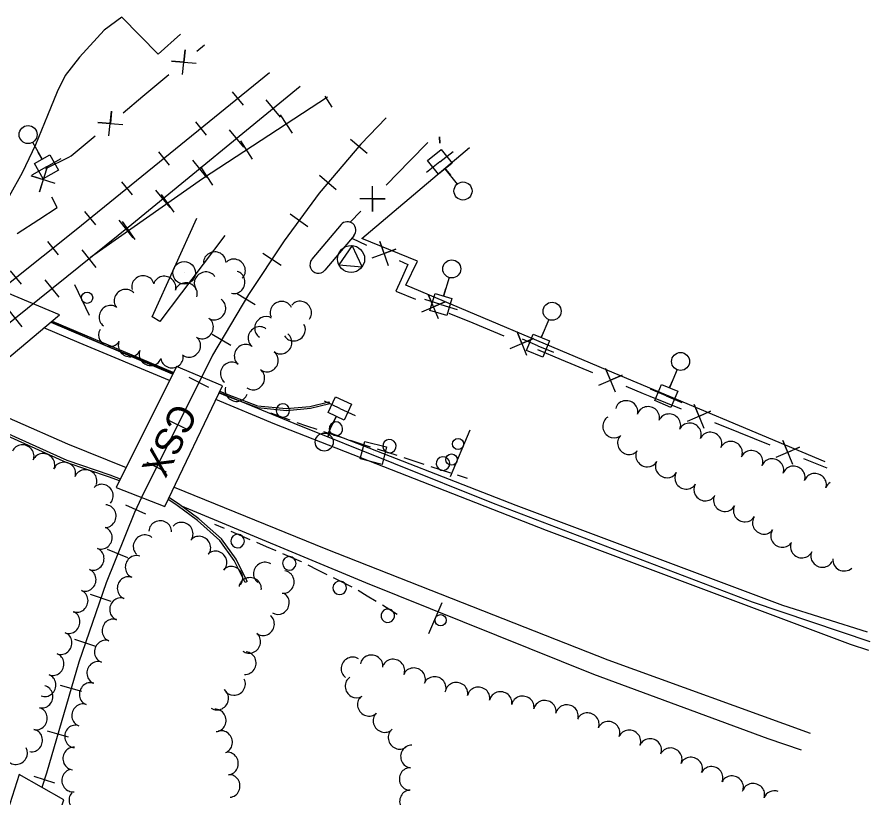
# Model space of a CAD drawing. Extents: x 1746010 to 1754829, y 655801 to 663091.
# Drawn here: x 1752063.6 to 1752442, y 658941.3 to 659287.8 of the extents above; entities that cross this region are included whole.
import ezdxf

# ---------------------------------------------------------------- set-up
doc = ezdxf.new("R2010")
doc.units = 0
for name, color, linetype in [('SURVEY - AERIAL SURVEY - Photo Control - Points - Elevations', 7, 'Continuous'), ('SURVEY - AERIAL SURVEY - Photo Control - Points - Locators', 7, 'Continuous'), ('SURVEY - AERIAL SURVEY - Photo Control - Points - Numbers', 7, 'Continuous'), ('SURVEY - AERIAL SURVEY - Photo Control with Text', 7, 'Continuous'), ('SURVEY - CENTERLINE - Existing Roads - Development', 7, 'Continuous'), ('SURVEY - CENTERLINE - Existing Roads Curve Text', 7, 'Continuous'), ('SURVEY - CENTERLINE - Existing Roads Text', 7, 'Continuous'), ('SURVEY - CENTERLINE - Preliminary - Development', 7, 'Continuous'), ('SURVEY - CONTROL - Points - Numbers', 7, 'Continuous')]:
    doc.layers.add(name, color=color, linetype=linetype)

msp = doc.modelspace()

# ---------------------------------------------------------------- linework, layer by layer
at = {"layer": 'SURVEY - AERIAL SURVEY - Photo Control - Points - Elevations'}
for points in [[(1752045.59, 659171.03), (1751992.27, 659126.33), (1752029.04, 659110.92), (1752082.37, 659155.62)], [(1752082.37, 659155.62), (1752045.59, 659171.03)], [(1752134.28, 659132.71), (1752107.47, 659078.99), (1752129.2, 659070.66), (1752154.72, 659124.15)], [(1752154.72, 659124.15), (1752134.28, 659132.71)], [(1752441.01, 659014.9), (1752403.45, 659026.77), (1752285.01, 659071.08), (1752202.29, 659103.35), (1752201.39, 659101.6)], [(1752064.54, 658951.68), (1752045.7, 658893.16), (1752065.48, 658882.04), (1752084.32, 658940.56)], [(1752084.32, 658940.56), (1752064.54, 658951.68)]]:
    msp.add_lwpolyline(points, dxfattribs=at)
at = {"layer": 'SURVEY - AERIAL SURVEY - Photo Control - Points - Locators'}
for p, q in [((1752164.02, 659248.7), (1752159.23, 659254.59)), ((1752173.98, 659251.09), (1752180.31, 659243.38)), ((1752203.39, 659247.84), (1752200.27, 659252.59)), ((1752185.73, 659236.29), (1752180.45, 659244.34)), ((1752147.63, 659235.41), (1752142.84, 659241.3)), ((1752157.67, 659237.71), (1752163.99, 659229.99)), ((1752168.07, 659224.74), (1752162.79, 659232.79)), ((1752218.9, 659227.18), (1752211.5, 659233.49)), ((1752131.24, 659222.12), (1752126.45, 659228.01)), ((1752141.35, 659224.33), (1752147.68, 659216.61)), ((1752150.41, 659213.19), (1752145.13, 659221.24)), ((1752205.23, 659211.11), (1752197.83, 659217.43)), ((1752114.85, 659208.83), (1752110.06, 659214.72)), ((1752125.04, 659210.95), (1752131.36, 659203.23)), ((1752133.23, 659201.24), (1752127.67, 659209.1)), ((1752098.46, 659195.54), (1752093.67, 659201.43)), ((1752192.65, 659194.65), (1752184.8, 659200.38)), ((1752108.74, 659197.63), (1752114.98, 659189.84)), ((1752115.94, 659189.13), (1752110.39, 659197)), ((1752081.97, 659182.33), (1752077.23, 659188.26)), ((1752092.28, 659184.43), (1752098.52, 659176.64)), ((1752180.69, 659177.55), (1752172.58, 659182.9)), ((1752065.45, 659169.2), (1752060.71, 659175.13)), ((1752075.81, 659171.23), (1752082.05, 659163.45)), ((1752169.24, 659160.09), (1752160.89, 659165.07)), ((1752059.42, 659158.11), (1752065.66, 659150.32)), ((1752158.42, 659141.98), (1752150.07, 659146.95)), ((1752148.6, 659123.48), (1752139.9, 659127.81)), ((1752139.27, 659104.67), (1752130.56, 659109)), ((1752129.93, 659085.87), (1752121.22, 659090.19)), ((1752120.65, 659067.19), (1752111.81, 659071.25)), ((1752112.76, 659047.88), (1752103.73, 659051.5)), ((1752105.3, 659028.44), (1752096.08, 659031.56)), ((1752098.45, 659008.49), (1752089.23, 659011.6)), ((1752092.24, 658988.58), (1752082.87, 658991.24)), ((1752086.36, 658968.32), (1752077, 658970.98)), ((1752080.35, 658947.94), (1752071.08, 658950.9))]:
    msp.add_line(p, q, dxfattribs=at)
for points in [[(1752136.1, 659280.15), (1752126.11, 659271.3), (1752110.04, 659287.75), (1752102.2, 659281.9), (1752091.24, 659269.92), (1752084.9, 659261.89), (1752081.32, 659254.58), (1752076.99, 659244.02), (1752071.76, 659231.08), (1752065.76, 659218.66), (1752060.06, 659208.3), (1752049.89, 659193.14), (1752034.39, 659176.02)], [(1752175.58, 659262.96), (1752089.81, 659193.42), (1752000.96, 659122.69)], [(1752015.68, 659116.52), (1752114.5, 659195.85), (1752189.13, 659257.06)], [(1752201.3, 659252.23), (1752145.79, 659215.92), (1752096.16, 659181.15)], [(1752227.3, 659243), (1752216.15, 659231.44), (1752197.6, 659209.66), (1752182.08, 659188.42), (1752166.33, 659164.7), (1752150.27, 659137.8), (1752118.76, 659074.66)], [(1752422.18, 659090.42), (1752328.48, 659129.79), (1752236.11, 659168.78), (1752241.3, 659179.5), (1752216.61, 659189.51), (1752264.37, 659229.85)], [(1752078.78, 659152.61), (1752102.62, 659142.14), (1752132.79, 659129.71)], [(1752131.22, 659126.56), (1752091.06, 659143.18), (1752075.5, 659149.86)], [(1752038.8, 659119.1), (1752085.97, 659098.47), (1752111.93, 659087.93)], [(1752153.33, 659121.25), (1752186.41, 659107.61), (1752274.81, 659072.14), (1752389.83, 659028.33), (1752442.04, 659010.77)], [(1752441.56, 659006.72), (1752433.41, 659009.47), (1752298.52, 659059.95), (1752177.99, 659107.21), (1752151.8, 659118.05)], [(1752133.29, 659079.25), (1752200.59, 659051.92), (1752325.72, 659002.58), (1752415.56, 658970.11)], [(1752118.76, 659074.66), (1752115.67, 659068.01), (1752103.04, 659036.84), (1752090.93, 659001.55), (1752076.65, 658952.3), (1752074.6, 658946.02)], [(1752136.07, 659071.01), (1752218.23, 659036.86), (1752319.33, 658996.32), (1752396.71, 658967.76), (1752411.5, 658962.71)]]:
    msp.add_lwpolyline(points, dxfattribs=at)
at = {"layer": 'SURVEY - AERIAL SURVEY - Photo Control - Points - Numbers'}
for points in [[(1752078.53, 659152.4), (1752132.42, 659129.49), (1752132.63, 659129.4)], [(1752079.15, 659152.92), (1752132.67, 659130.16), (1752132.95, 659130.04)], [(1752153.26, 659121.1), (1752156.86, 659119.65), (1752170.24, 659114.49), (1752183.34, 659113.29), (1752193.84, 659114.28), (1752202.37, 659116.26), (1752201.98, 659117.01)], [(1752153.57, 659121.74), (1752157.02, 659120.35), (1752170.23, 659115.24), (1752183.16, 659114.06), (1752193.5, 659115.05), (1752201.98, 659117.01)], [(1752109.39, 659082.83), (1752104.92, 659084.53), (1752085.74, 659091.09), (1752064.47, 659100.61), (1752039.79, 659111.74), (1752033.25, 659114.45)], [(1752108.95, 659081.96), (1752104.6, 659083.62), (1752085.4, 659090.18), (1752064.05, 659099.73), (1752039.37, 659110.87), (1752032.42, 659113.75)], [(1752184.78, 659108.9), (1752176.12, 659112.01)], [(1752192.21, 659106.22), (1752187.79, 659107.81)], [(1752196.68, 659104.76), (1752192.22, 659106.21), (1752192.21, 659106.22)], [(1752208.47, 659100.92), (1752199.72, 659103.77)], [(1752215.98, 659098.48), (1752211.51, 659099.93)], [(1752220.45, 659097.02), (1752215.98, 659098.48)], [(1752232.24, 659093.19), (1752223.49, 659096.03)], [(1752239.75, 659090.74), (1752235.28, 659092.2)], [(1752244.22, 659089.29), (1752239.75, 659090.74)], [(1752256.01, 659085.45), (1752247.26, 659088.3)], [(1752263.52, 659083.01), (1752259.05, 659084.46)], [(1752165.63, 659037.41), (1752164.74, 659036.98), (1752159.91, 659046.7), (1752153.5, 659055.61), (1752143.56, 659064.39), (1752134.58, 659071.02), (1752130.88, 659073.57), (1752130.63, 659073.66)], [(1752165.63, 659037.41), (1752160.75, 659047.21), (1752154.24, 659056.26), (1752144.2, 659065.13), (1752135.23, 659071.75), (1752131.42, 659074.4), (1752131.05, 659074.54)], [(1752151.1, 659062.82), (1752155.42, 659060.95)], [(1752158.36, 659059.69), (1752166.81, 659056.04)], [(1752169.74, 659054.77), (1752174.06, 659052.91)], [(1752174.06, 659052.91), (1752178.38, 659051.05)], [(1752181.31, 659049.78), (1752189.66, 659046.18), (1752189.76, 659046.13)], [(1752192.62, 659044.7), (1752196.83, 659042.6)], [(1752196.83, 659042.6), (1752201.03, 659040.5)], [(1752203.9, 659039.08), (1752212.13, 659034.97)], [(1752214.97, 659033.51), (1752218.98, 659031.06)], [(1752218.98, 659031.06), (1752222.99, 659028.61)], [(1752225.72, 659026.95), (1752232.29, 659022.93)]]:
    msp.add_lwpolyline(points, dxfattribs=at)
for centre, start, end in [((1752181.5, 659113.2), 3.0135, 2.9995), ((1752205.05, 659105.13), 4.8134, 4.7994), ((1752228.83, 659097.39), 4.8134, 4.7994), ((1752252.6, 659089.65), 4.8134, 4.7994), ((1752161.43, 659055.29), 178.6725, 178.6585), ((1752184.38, 659045.38), 178.6725, 178.6585), ((1752206.7, 659034.53), 175.4564, 175.4424), ((1752228.09, 659022.19), 170.5093, 170.4953)]:
    msp.add_arc(centre, 3, start, end, dxfattribs=at)
at = {"layer": 'SURVEY - AERIAL SURVEY - Photo Control with Text'}
for p, q in [((1752137.76, 659174.24), (1752137.76, 659174.24)), ((1752095.68, 659155.35), (1752089.24, 659168.9)), ((1752264.45, 659104.46), (1752255.8, 659083.8)), ((1752246.28, 659014.23), (1752252.26, 659027.98))]:
    msp.add_line(p, q, dxfattribs=at)
msp.add_lwpolyline([(1752155.69, 659190.8), (1752126.95, 659152.74), (1752123.47, 659154.78), (1752143.39, 659198.59)], dxfattribs=at)
for centre, radius in [((1752137.75, 659174.28), 5), ((1752094.65, 659163.22), 2.5), ((1752259.24, 659098.36), 2.5), ((1752256.34, 659091.44), 2.5), ((1752251.53, 659020.17), 2.5)]:
    msp.add_circle(centre, radius, dxfattribs=at)
at = {"layer": 'SURVEY - CENTERLINE - Existing Roads - Development'}
for p, q in [((1752207.34, 659195.68), (1752194.41, 659180.29)), ((1752213.08, 659190.86), (1752200.16, 659175.46)), ((1752212.3, 659186.4), (1752206.36, 659177.86)), ((1752216.72, 659176.99), (1752212.3, 659186.4)), ((1752206.36, 659177.86), (1752216.72, 659176.99))]:
    msp.add_line(p, q, dxfattribs=at)
for points in [[(1752143.26, 659272.55), (1752146.79, 659275.49)], [(1752137, 659262.23), (1752138.19, 659273.18), (1752137.63, 659267.74), (1752132.12, 659268.13), (1752143.07, 659267.28)], [(1752119.36, 659252.64), (1752130.89, 659262.24)], [(1752110.6, 659245.34), (1752119.36, 659252.64)], [(1752104.35, 659235.02), (1752105.53, 659245.98), (1752104.98, 659240.53), (1752099.46, 659240.92), (1752110.42, 659240.08)], [(1752086.57, 659225.66), (1752087.54, 659226.13), (1752098.23, 659235.04)], [(1752245.89, 659232.06), (1752237.91, 659223.92)], [(1752251.08, 659234.57), (1752251.12, 659231.82), (1752251.06, 659234.58)], [(1752076.33, 659220.64), (1752086.57, 659225.66)], [(1752080.51, 659213.92), (1752069.82, 659217.29), (1752075.14, 659215.65), (1752073.44, 659210.27), (1752076.88, 659220.94)], [(1752237.91, 659223.92), (1752227.4, 659213.21)], [(1752221.18, 659212.72), (1752221.36, 659201.48), (1752221.24, 659207.07), (1752226.89, 659207.12), (1752215.65, 659207.08)], [(1752073.21, 659197.9), (1752081.42, 659203.25), (1752079.04, 659207.87)], [(1752216.13, 659201.71), (1752211.31, 659196.81)], [(1752063.66, 659191.68), (1752073.21, 659197.9)], [(1752212.1, 659189.69), (1752218.61, 659186.63)], [(1752221.12, 659180.92), (1752231.68, 659184.8), (1752226.44, 659182.84), (1752224.53, 659188.16), (1752228.27, 659177.56)], [(1752233.18, 659179.78), (1752236.9, 659178.04), (1752233.95, 659171.36)], [(1752233.95, 659171.36), (1752231.69, 659166.21), (1752240.34, 659162.62)], [(1752243.12, 659157.04), (1752253.48, 659161.41), (1752248.35, 659159.2), (1752246.18, 659164.43), (1752250.42, 659154.02)], [(1752255.22, 659156.47), (1752265.76, 659152.11)], [(1752265.76, 659152.11), (1752279.61, 659146.37)], [(1752282.39, 659140.78), (1752292.75, 659145.16), (1752287.62, 659142.95), (1752285.45, 659148.18), (1752289.69, 659137.76)], [(1752294.49, 659140.21), (1752305.03, 659135.85)], [(1752305.03, 659135.85), (1752318.89, 659130.12)], [(1752321.66, 659124.53), (1752332.02, 659128.9), (1752326.89, 659126.7), (1752324.72, 659131.92), (1752328.96, 659121.51)], [(1752333.76, 659123.96), (1752341.44, 659120.78), (1752344.3, 659119.62)], [(1752344.3, 659119.62), (1752358.2, 659113.98)], [(1752361.01, 659108.42), (1752371.34, 659112.86), (1752366.22, 659110.62), (1752364.02, 659115.83), (1752368.33, 659105.45)], [(1752373.12, 659107.94), (1752383.68, 659103.65)], [(1752383.68, 659103.65), (1752397.58, 659098.02)], [(1752400.39, 659092.45), (1752410.72, 659096.9), (1752405.6, 659094.66), (1752403.4, 659099.87), (1752407.71, 659089.48)], [(1752412.49, 659091.97), (1752422.84, 659087.77)]]:
    msp.add_lwpolyline(points, dxfattribs=at)
msp.add_circle((1752211.79, 659180.42), 6, dxfattribs=at)
for centre, start, end in [((1752210.18, 659193.23), 319.9851, 139.9851), ((1752197.25, 659177.84), 139.9851, 319.9851)]:
    msp.add_arc(centre, 3.75, start, end, dxfattribs=at)
at = {"layer": 'SURVEY - CENTERLINE - Existing Roads Curve Text'}
for p, q in [((1752070.4, 659232.24), (1752074.7, 659224.67)), ((1752251.18, 659223.51), (1752257.05, 659228.18)), ((1752074.5, 659225.02), (1752072.92, 659227.8)), ((1752076.63, 659221.28), (1752083.15, 659224.99)), ((1752076.63, 659221.28), (1752070.11, 659217.58)), ((1752251.18, 659223.51), (1752245.31, 659218.84)), ((1752259.02, 659213.64), (1752253.61, 659220.45)), ((1752253.86, 659220.14), (1752255.85, 659217.64)), ((1752255.32, 659172.29), (1752252.79, 659163.97)), ((1752252.91, 659164.35), (1752253.84, 659167.41)), ((1752251.65, 659160.23), (1752244.48, 659162.42)), ((1752251.65, 659160.23), (1752258.83, 659158.05)), ((1752299.51, 659153.62), (1752296.21, 659145.57)), ((1752296.36, 659145.94), (1752297.57, 659148.9)), ((1752294.73, 659141.96), (1752287.79, 659144.81)), ((1752294.73, 659141.96), (1752301.67, 659139.12)), ((1752356.48, 659131.36), (1752353.13, 659123.32)), ((1752353.28, 659123.69), (1752354.52, 659126.65)), ((1752351.63, 659119.72), (1752344.71, 659122.61)), ((1752351.63, 659119.72), (1752358.55, 659116.84)), ((1752206.8, 659114.17), (1752199.99, 659117.31)), ((1752201.51, 659102.73), (1752205.16, 659110.62)), ((1752206.8, 659114.17), (1752213.6, 659111.02)), ((1752204.99, 659110.26), (1752203.65, 659107.36))]:
    msp.add_line(p, q, dxfattribs=at)
for points in [[(1752251.81, 659228.99), (1752256.66, 659222.88), (1752250.56, 659218.03), (1752245.7, 659224.14)], [(1752075.17, 659215.96), (1752071.31, 659222.74), (1752078.09, 659226.6), (1752081.95, 659219.82)], [(1752246.79, 659157.64), (1752249.06, 659165.1), (1752256.52, 659162.83), (1752254.25, 659155.37)], [(1752289.64, 659139.83), (1752292.6, 659147.05), (1752299.82, 659144.09), (1752296.86, 659136.87)], [(1752346.53, 659117.62), (1752349.53, 659124.82), (1752356.73, 659121.82), (1752353.73, 659114.62)], [(1752211.97, 659116.07), (1752208.7, 659108.99), (1752201.62, 659112.26), (1752204.89, 659119.34)]]:
    msp.add_lwpolyline(points, close=True, dxfattribs=at)
for centre in [(1752068.47, 659235.63), (1752261.45, 659210.59), (1752256.46, 659176.02), (1752300.99, 659157.23), (1752357.98, 659134.96), (1752199.87, 659099.19)]:
    msp.add_circle(centre, 4, dxfattribs=at)
at = {"layer": 'SURVEY - CENTERLINE - Existing Roads Text'}
for centre, major_axis, start_param, end_param in [((1752151.29, 659178.87), (5, 0.02), 0, 3.141593), ((1752160.03, 659175.52), (3.42, -3.65), 0, 3.141593), ((1752147.13, 659169.89), (4.24, 2.65), 0, 3.141593), ((1752119.4, 659168.29), (4.82, 1.33), 0, 3.141593), ((1752129.01, 659168.04), (4.8, -1.41), 0, 3.141593), ((1752159.98, 659170.07), (-1.23, -4.85), 0, 3.141593), ((1752111.52, 659162.14), (3.82, 3.22), 0, 3.141593), ((1752138.58, 659165.14), (4.77, -1.5), 0, 3.141593), ((1752104.73, 659154.92), (2.85, 4.11), 0, 3.141593), ((1752151.36, 659158.32), (-2.74, -4.18), 0, 3.141593), ((1752180.81, 659156.84), (4.53, 2.12), 0, 3.141593), ((1752189.35, 659156.88), (3.91, -3.12), 0, 3.141593), ((1752145.88, 659149.95), (-2.74, -4.18), 0, 3.141593), ((1752173.8, 659149.97), (2.7, 4.21), 0, 3.141593), ((1752104.63, 659146.48), (-4.24, 2.66), 0, 3.141593), ((1752170.93, 659145.54), (3.08, 3.94), 0, 3.141593), ((1752186.57, 659148.84), (-4.29, -2.57), 0, 3.141593), ((1752140.18, 659141.75), (-3.15, -3.88), 0, 3.141593), ((1752180.73, 659143.18), (-3.03, -3.98), 0, 3.141593), ((1752113.44, 659141.81), (-4.59, 1.99), 0, 3.141593), ((1752164.78, 659137.66), (3.08, 3.94), 0, 3.141593), ((1752122.67, 659137.95), (-4.63, 1.9), 0, 3.141593), ((1752132.3, 659136.87), (-4.97, -0.55), 0, 3.141593), ((1752174.67, 659135.23), (-3.03, -3.98), 0, 3.141593), ((1752158.63, 659129.77), (3.08, 3.94), 0, 3.141593), ((1752168.62, 659127.29), (-3.03, -3.98), 0, 3.141593), ((1752160.86, 659121.99), (-4.75, 1.55), 0, 3.141593), ((1752334.05, 659112.86), (4.82, -1.32), 0, 3.141593), ((1752343.69, 659110.22), (4.82, -1.32), 0, 3.141593), ((1752353.1, 659106.93), (4.57, -2.03), 0, 3.141593), ((1752328.28, 659105.98), (-2.56, 4.3), 0, 3.141593), ((1752362.23, 659102.88), (4.57, -2.03), 0, 3.141593), ((1752371.37, 659098.82), (4.57, -2.03), 0, 3.141593), ((1752334.88, 659098.56), (-3.56, 3.51), 0, 3.141593), ((1752380.5, 659094.76), (4.57, -2.03), 0, 3.141593), ((1752066.12, 659093.26), (4.6, -1.95), 0, 3.141593), ((1752389.63, 659090.7), (4.57, -2.03), 0, 3.141593), ((1752075.33, 659089.35), (4.6, -1.95), 0, 3.141593), ((1752343.04, 659092.97), (-4.38, 2.41), 0, 3.141593), ((1752398.84, 659087.04), (4.73, -1.63), 0, 3.141593), ((1752084.57, 659085.54), (4.72, -1.66), 0, 3.141593), ((1752351.76, 659088.16), (-4.38, 2.41), 0, 3.141593), ((1752408.29, 659083.79), (4.73, -1.63), 0, 3.141593), ((1752094, 659082.21), (4.72, -1.66), 0, 3.141593), ((1752360.32, 659083.13), (-4.25, 2.63), 0, 3.141593), ((1752417.75, 659080.54), (4.73, -1.63), 0, 3.141593), ((1752101.38, 659075.64), (3.58, -3.49), 0, 3.141593), ((1752368.76, 659077.91), (-4.25, 2.63), 0, 3.141593), ((1752427.2, 659077.29), (4.73, -1.63), 2.470662, 3.141593), ((1752377.54, 659073.17), (-4.44, 2.31), 0, 3.141593), ((1752102.78, 659066.37), (-0.2, -5), 0, 3.141593), ((1752386.4, 659068.56), (-4.44, 2.31), 0, 3.141593), ((1752394.81, 659063.19), (-4.06, 2.92), 0, 3.141593), ((1752127.1, 659059.58), (5, -0.18), 0, 3.141593), ((1752136.77, 659058.78), (3.92, -3.11), 0, 3.141593), ((1752101, 659056.67), (-1.78, -4.67), 0, 3.141593), ((1752119.96, 659053.19), (3.39, 3.68), 0, 3.141593), ((1752144.59, 659052.59), (3.92, -3.11), 0, 3.141593), ((1752402.93, 659057.35), (-4.06, 2.92), 0, 3.141593), ((1752411.67, 659052.59), (-4.55, 2.07), 0, 3.141593), ((1752097.43, 659047.33), (-1.78, -4.67), 0, 3.141593), ((1752151.85, 659045.97), (3.52, -3.55), 0, 3.141593), ((1752420.77, 659048.44), (-4.55, 2.07), 0, 3.141593), ((1752116.31, 659043.9), (1.77, 4.67), 0, 3.141593), ((1752173.27, 659041.03), (2.86, 4.1), 0, 3.141593), ((1752430.59, 659046.74), (-4.95, 0.72), 0, 2.44652), ((1752093.87, 659037.99), (-1.78, -4.67), 0, 3.141593), ((1752158.87, 659039.17), (3.72, -3.34), 0, 3.141593), ((1752112.76, 659034.55), (1.77, 4.67), 0, 3.141593), ((1752167, 659034.36), (4.95, -0.72), 0, 3.141593), ((1752181.79, 659037.12), (-0.63, -4.96), 0, 3.141593), ((1752090.3, 659028.64), (-1.78, -4.67), 0, 3.141593), ((1752179.55, 659027.69), (-2.71, -4.2), 0, 3.141593), ((1752109.39, 659025.14), (1.68, 4.71), 0, 3.141593), ((1752086.73, 659019.3), (-1.78, -4.67), 0, 3.141593), ((1752106.03, 659015.73), (1.68, 4.71), 0, 3.141593), ((1752172.92, 659018.24), (-3.07, -3.94), 0, 3.141593), ((1752083.17, 659009.96), (-1.78, -4.67), 0, 3.141593), ((1752166.82, 659010.41), (-3.07, -3.94), 0, 3.141593), ((1752102.66, 659006.32), (1.68, 4.71), 0, 3.141593), ((1752079.6, 659000.62), (-1.78, -4.67), 0, 3.141593), ((1752164.9, 659001.13), (-0.39, -4.99), 0, 3.141593), ((1752220.87, 659000.05), (4.94, -0.76), 0, 3.141593), ((1752099.3, 658996.9), (1.68, 4.71), 0, 3.141593), ((1752212.2, 658998.92), (2.85, 4.11), 0, 3.141593), ((1752230.63, 658998.13), (4.61, -1.95), 0, 3.141593), ((1752239.81, 658994.25), (4.61, -1.95), 0, 3.141593), ((1752076.03, 658991.28), (-1.78, -4.67), 0, 3.141593), ((1752159.95, 658991.66), (-4.39, -2.39), 0, 3.141593), ((1752213.96, 658990.68), (-2.67, 4.23), 0, 3.141593), ((1752248.98, 658990.37), (4.61, -1.95), 0, 3.141593), ((1752074.71, 658986.23), (-1.24, -4.84), 0, 3.141593), ((1752095.94, 658987.49), (1.68, 4.71), 0, 3.141593), ((1752258.61, 658987.85), (4.89, -1.04), 0, 3.141593), ((1752268.39, 658985.78), (4.89, -1.04), 0, 3.141593), ((1752152.59, 658985.29), (-2.85, -4.11), 0, 3.141593), ((1752219.5, 658982.48), (-3.48, 3.59), 0, 3.141593), ((1752278.18, 658983.73), (4.91, -0.97), 0, 3.141593), ((1752287.98, 658981.8), (4.91, -0.97), 0, 3.141593), ((1752092.58, 658978.08), (1.68, 4.71), 0, 3.141593), ((1752297.79, 658979.87), (4.91, -0.97), 0, 3.141593), ((1752307.6, 658977.94), (4.91, -0.97), 0, 3.141593), ((1752072.23, 658976.55), (-1.24, -4.84), 0, 3.141593), ((1752151.59, 658975.75), (0.28, -4.99), 0, 3.141593), ((1752226.45, 658975.3), (-3.48, 3.59), 0, 3.141593), ((1752316.9, 658974.33), (4.62, -1.91), 0, 3.141593), ((1752326.14, 658970.51), (4.62, -1.91), 0, 3.141593), ((1752070.13, 658966.81), (-0.9, -4.92), 0, 3.141593), ((1752089.38, 658968.64), (0.39, 4.98), 0, 3.141593), ((1752154.4, 658966.2), (1.61, -4.73), 0, 3.141593), ((1752233.1, 658967.87), (-3.08, 3.94), 0, 3.141593), ((1752335.38, 658966.7), (4.62, -1.91), 0, 3.141593), ((1752344.63, 658962.88), (4.62, -1.91), 0, 3.141593), ((1752063.27, 658961.01), (-4.31, -2.54), 0, 3.141593), ((1752088.61, 658958.86), (0.39, 4.98), 0, 3.141593), ((1752238.48, 658959.76), (0.27, 4.99), 0, 3.141593), ((1752353.71, 658958.76), (4.55, -2.07), 0, 3.141593), ((1752157.04, 658956.62), (0.37, -4.99), 0, 3.141593), ((1752362.79, 658954.63), (4.55, -2.07), 0, 3.141593), ((1752371.87, 658950.51), (4.55, -2.07), 0, 3.141593), ((1752088.13, 658949.06), (-0.75, 4.94), 0, 3.141593), ((1752157.78, 658946.66), (0.37, -4.99), 0, 3.141593), ((1752237.93, 658949.77), (0.27, 4.99), 0, 3.141593), ((1752380.95, 658946.38), (4.55, -2.07), 0, 3.141593), ((1752390.36, 658943.02), (4.73, -1.62), 0, 3.141593), ((1752238.04, 658939.78), (-0.1, 5), 0, 3.141593), ((1752399.82, 658939.79), (4.73, -1.62), 1.571407, 3.141593), ((1752091.47, 658940.2), (-3.68, 3.38), 0, 3.141593)]:
    msp.add_ellipse(centre, major_axis=major_axis, ratio=0.940188, start_param=start_param, end_param=end_param, dxfattribs=at)
at = {"layer": 'SURVEY - CENTERLINE - Preliminary - Development'}
msp.add_line((1752221.69, 659094.39), (1752221.69, 659094.39), dxfattribs=at)
msp.add_lwpolyline([(1752215.85, 659091.74), (1752217.82, 659099.5), (1752227.52, 659097.03), (1752225.54, 659089.28), (1752215.85, 659091.74)], dxfattribs=at)

# ---------------------------------------------------------------- texts
at = {"layer": 'SURVEY - CONTROL - Points - Numbers'}
msp.add_text('CSX', height=12, rotation=243.4776, dxfattribs=at).set_placement((1752133.32, 659117.33))

doc.saveas('drawing.dxf')
